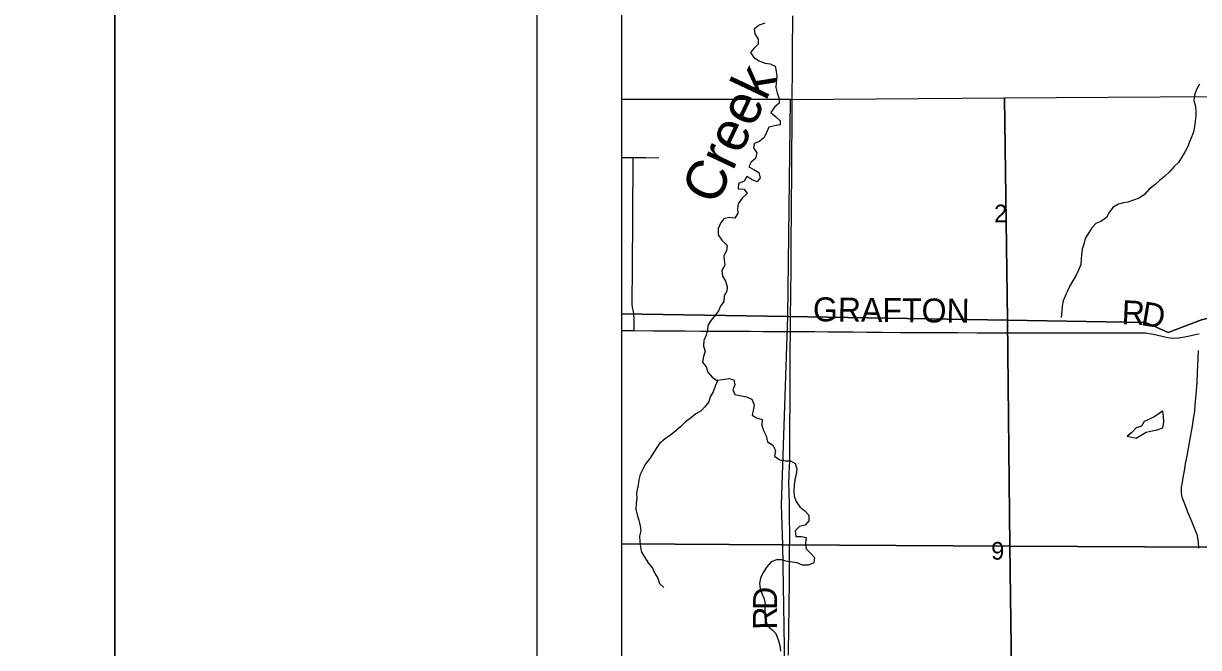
# Model space of a CAD drawing. Extents: x 0 to 34, y 0 to 22.
# Drawn here: x 1.392 to 2.784, y 19.522 to 20.261 of the extents above; entities that cross this region are included whole.
import ezdxf

# ---------------------------------------------------------------- set-up
doc = ezdxf.new("R2010")
doc.units = 0
for name, color, linetype in [('Default', 7, 'Continuous'), ('GM_X_County_Road', 7, 'Continuous'), ('GM_X_County_Road_Text', 7, 'Continuous'), ('GM_X_Minor_Lake', 7, 'Continuous'), ('GM_X_Minor_River', 7, 'Continuous'), ('GM_X_Minor_River_Text', 7, 'Continuous'), ('GM_X_Rail_Line_Text', 7, 'Continuous'), ('GM_X_Section', 7, 'Continuous'), ('GM_X_Section_Text', 7, 'Continuous'), ('GM_X_Township_Road', 7, 'Continuous'), ('SH_Border', 7, 'Continuous'), ('SH_Cut_Line', 7, 'Continuous'), ('SH_Data', 7, 'Continuous')]:
    doc.layers.add(name, color=color, linetype=linetype)

msp = doc.modelspace()

# ---------------------------------------------------------------- linework, layer by layer
at = {"layer": 'Default'}
for points in [[(2.1, 20.1712), (2.1, 19.9174), (2.2971, 19.9141), (2.3001, 20.1712)], [(2.1, 19.9174), (2.1, 19.6448), (2.2913, 19.6437), (2.2898, 19.6911), (2.2971, 19.9141)], [(2.1, 19.6448), (2.1, 19.3789), (2.2957, 19.377), (2.2913, 19.6437)]]:
    msp.add_lwpolyline(points, close=True, dxfattribs=at)
at = {"layer": 'GM_X_County_Road'}
for points in [[(2.298, 19.5128), (2.2981, 19.5252), (2.2982, 19.5351), (2.2984, 19.5502), (2.2987, 19.5642), (2.2988, 19.5786), (2.299, 19.5946), (2.2991, 19.6052), (2.2991, 19.6157), (2.2992, 19.6275), (2.2993, 19.6366), (2.2994, 19.653), (2.2992, 19.679), (2.2992, 19.6895), (2.2987, 19.7071), (2.2985, 19.7168), (2.2987, 19.7257), (2.2993, 19.7382), (2.2994, 19.7405), (2.2995, 19.7524), (2.2997, 19.7647), (2.2997, 19.7814), (2.2999, 19.8154), (2.3, 19.8722), (2.3001, 19.8963), (2.3003, 19.9204), (2.3005, 19.9322), (2.3006, 19.9441), (2.3009, 19.9677), (2.3009, 19.9842), (2.3012, 20.0153), (2.3013, 20.027), (2.3014, 20.039), (2.3016, 20.0578), (2.3017, 20.0721), (2.3018, 20.0918), (2.3019, 20.1113), (2.3021, 20.1363), (2.3024, 20.1609), (2.3024, 20.1749), (2.3026, 20.2063), (2.3027, 20.2284), (2.3028, 20.2424), (2.303, 20.2559), (2.3032, 20.2704)], [(2.1, 19.8976), (2.1042, 19.8976), (2.1151, 19.8974), (2.1373, 19.8973), (2.1562, 19.8972), (2.1755, 19.897), (2.194, 19.8969), (2.2082, 19.8967), (2.2323, 19.8967), (2.253, 19.8966), (2.2675, 19.8965), (2.2839, 19.8964), (2.3001, 19.8963), (2.315, 19.8962), (2.3291, 19.8962), (2.3446, 19.8961), (2.3604, 19.896), (2.3745, 19.8959), (2.3913, 19.8957), (2.4083, 19.8955), (2.4302, 19.8953), (2.4398, 19.8952), (2.4493, 19.8951), (2.4984, 19.895), (2.5215, 19.8949), (2.5406, 19.8949), (2.5555, 19.8948), (2.5721, 19.8947), (2.5896, 19.8946), (2.6903, 19.8947), (2.7038, 19.8948), (2.7149, 19.8949), (2.7186, 19.8948), (2.7211, 19.8946), (2.7253, 19.894), (2.7321, 19.8927), (2.7436, 19.8899), (2.7474, 19.8891), (2.7501, 19.8887), (2.7528, 19.8885), (2.7604, 19.8889), (2.7669, 19.8899), (2.7749, 19.8917), (2.7813, 19.893), (2.7845, 19.8934)]]:
    msp.add_lwpolyline(points, dxfattribs=at)
at = {"layer": 'GM_X_Minor_Lake'}
for points in [[(2.741, 19.8018), (2.7317, 19.7955), (2.7255, 19.7925), (2.7194, 19.7898), (2.7162, 19.7841), (2.7097, 19.7824), (2.7048, 19.7767), (2.6989, 19.7721)], [(2.699, 19.7722), (2.7099, 19.7698), (2.7158, 19.7737), (2.7217, 19.7769), (2.7285, 19.7786), (2.7348, 19.78), (2.7414, 19.7823), (2.7427, 19.7891), (2.7422, 19.7958), (2.7412, 19.8018)], [(2.6991, 19.7722), (2.7099, 19.7698), (2.7158, 19.7737), (2.7217, 19.7769), (2.7285, 19.7786), (2.7348, 19.78), (2.7414, 19.7823), (2.7427, 19.7891), (2.7422, 19.7958), (2.7412, 19.8019)], [(2.7412, 19.8019), (2.7317, 19.7955), (2.7255, 19.7925), (2.7194, 19.7898), (2.7162, 19.7841), (2.7097, 19.7824), (2.7048, 19.7767), (2.6991, 19.7722)]]:
    msp.add_lwpolyline(points, dxfattribs=at)
at = {"layer": 'GM_X_Minor_River'}
for points in [[(2.2697, 20.2616), (2.2633, 20.2593), (2.2574, 20.2547), (2.258, 20.2489), (2.262, 20.2426), (2.262, 20.2367), (2.2568, 20.2318), (2.2529, 20.227), (2.2569, 20.2211), (2.2631, 20.2172), (2.2698, 20.2143), (2.2762, 20.2134), (2.2823, 20.2107), (2.2834, 20.2049), (2.284, 20.1984), (2.2833, 20.1919), (2.2829, 20.1855), (2.2846, 20.1792), (2.2865, 20.1732), (2.2867, 20.1667), (2.2814, 20.1623), (2.2769, 20.1557), (2.283, 20.1507), (2.2879, 20.146), (2.2879, 20.1413), (2.2813, 20.1401), (2.2746, 20.1384), (2.272, 20.1323), (2.2691, 20.1262), (2.2637, 20.1214), (2.2574, 20.1191), (2.2566, 20.1138), (2.2603, 20.1081), (2.2589, 20.1015), (2.2538, 20.0971), (2.2508, 20.0914), (2.2567, 20.0882), (2.2628, 20.0846), (2.2645, 20.0783), (2.2607, 20.0736), (2.255, 20.076), (2.2487, 20.0798), (2.2453, 20.0743), (2.2387, 20.0718), (2.2385, 20.0653), (2.2453, 20.065), (2.2491, 20.0597), (2.2431, 20.0545), (2.2385, 20.0477), (2.2376, 20.0416), (2.2378, 20.0367), (2.2344, 20.0308), (2.2279, 20.0313), (2.2213, 20.0298), (2.2173, 20.0247), (2.2145, 20.0178), (2.2145, 20.011), (2.2191, 20.0045), (2.2253, 19.9983), (2.2246, 19.992), (2.2214, 19.9861), (2.2217, 19.9814), (2.2227, 19.9749), (2.2189, 19.9686), (2.2199, 19.9618), (2.2235, 19.9559), (2.2254, 19.9491), (2.225, 19.9443), (2.2216, 19.9386), (2.2213, 19.9318), (2.2175, 19.9265), (2.2152, 19.9208), (2.2108, 19.9151), (2.2059, 19.9092), (2.2025, 19.9033), (2.2018, 19.8985)], [(2.7846, 20.1894), (2.7814, 20.1829), (2.779, 20.1764), (2.7782, 20.17), (2.7799, 20.1631), (2.7803, 20.1565), (2.7805, 20.1518), (2.7796, 20.1455), (2.7788, 20.1394), (2.7775, 20.1329), (2.7751, 20.1267), (2.7724, 20.1204), (2.7711, 20.1156), (2.7679, 20.1096), (2.7643, 20.1037), (2.7599, 20.0964), (2.7548, 20.0919), (2.7491, 20.0856), (2.7433, 20.0801), (2.7374, 20.0751), (2.7319, 20.0701), (2.7253, 20.0648), (2.7198, 20.0587), (2.7131, 20.0545), (2.7067, 20.0518), (2.6999, 20.0495), (2.6949, 20.0488), (2.6887, 20.0472), (2.6822, 20.0434), (2.6777, 20.0373), (2.6745, 20.0316), (2.668, 20.0265), (2.662, 20.0244), (2.6574, 20.0192), (2.6532, 20.013), (2.6493, 20.0067), (2.6478, 20), (2.6459, 19.9938), (2.6448, 19.9873), (2.6446, 19.9825), (2.6442, 19.9757), (2.6416, 19.9691), (2.6385, 19.963)], [(2.6385, 19.963), (2.6353, 19.9571), (2.6313, 19.9504), (2.6285, 19.9447), (2.6255, 19.9382), (2.6234, 19.9325), (2.6221, 19.9265), (2.6215, 19.9204), (2.6208, 19.9128)], [(2.2018, 19.8985), (2.2004, 19.8921), (2.1978, 19.8856), (2.1974, 19.8791), (2.1991, 19.8732), (2.1973, 19.8668), (2.1959, 19.8599), (2.2005, 19.8543), (2.2024, 19.848), (2.2077, 19.8421), (2.2138, 19.8378), (2.2112, 19.8315), (2.2087, 19.825), (2.2051, 19.8191), (2.2034, 19.8131), (2.1989, 19.8072), (2.1943, 19.8022), (2.1883, 19.799), (2.182, 19.7936), (2.1761, 19.7892), (2.1703, 19.7839), (2.1644, 19.7786), (2.1581, 19.7736), (2.1517, 19.7692), (2.1452, 19.7637), (2.142, 19.759), (2.1337, 19.746), (2.129, 19.7399), (2.1254, 19.7331), (2.1223, 19.7268), (2.1206, 19.7207), (2.1197, 19.7143), (2.1188, 19.7093), (2.118, 19.7046), (2.1182, 19.6987), (2.1175, 19.6922), (2.1169, 19.6858), (2.1188, 19.6793), (2.1207, 19.6727), (2.1221, 19.6662), (2.123, 19.66), (2.1215, 19.6539), (2.1219, 19.6474), (2.1227, 19.641), (2.124, 19.6351), (2.1278, 19.6285), (2.1318, 19.6222), (2.1369, 19.6161), (2.1394, 19.6104), (2.143, 19.6042), (2.1453, 19.5979), (2.1504, 19.593)], [(2.2126, 19.8387), (2.2202, 19.8395), (2.2271, 19.8407), (2.2333, 19.839), (2.2345, 19.8333), (2.2318, 19.8272), (2.2343, 19.8219), (2.248, 19.8189), (2.2544, 19.8162), (2.2571, 19.8096), (2.2562, 19.8029), (2.2548, 19.7971), (2.2602, 19.7942), (2.2668, 19.792), (2.2664, 19.7855), (2.2685, 19.7789), (2.2716, 19.7726), (2.2729, 19.7658), (2.2792, 19.7616), (2.2824, 19.7554), (2.2813, 19.7485), (2.2877, 19.7442), (2.294, 19.743), (2.3003, 19.7432), (2.3059, 19.74), (2.3079, 19.7338), (2.3069, 19.7269), (2.3056, 19.721), (2.3047, 19.7142), (2.3041, 19.7074), (2.3047, 19.7013), (2.3072, 19.6948), (2.3113, 19.6888), (2.3172, 19.6839), (2.322, 19.6787), (2.3222, 19.6721), (2.3178, 19.667), (2.311, 19.6652), (2.3057, 19.6601), (2.3065, 19.6534), (2.3133, 19.6536), (2.3188, 19.6521), (2.318, 19.6457), (2.3188, 19.6389), (2.3241, 19.6337), (2.3289, 19.6286), (2.3281, 19.6222), (2.3213, 19.6197), (2.3147, 19.6195), (2.3082, 19.6221), (2.3018, 19.6232), (2.2949, 19.6244), (2.2902, 19.6257), (2.2837, 19.626), (2.2775, 19.6234), (2.2724, 19.6175), (2.268, 19.6108), (2.2648, 19.6043), (2.2637, 19.5979), (2.2644, 19.592), (2.2663, 19.5859), (2.2692, 19.5798), (2.2702, 19.5734), (2.2698, 19.5667), (2.27, 19.5601), (2.2709, 19.5538), (2.2732, 19.5476), (2.2784, 19.543), (2.283, 19.5384)], [(2.283, 19.5384), (2.2856, 19.5312), (2.2877, 19.5243), (2.2883, 19.5175)]]:
    msp.add_lwpolyline(points, dxfattribs=at)
at = {"layer": 'GM_X_Rail_Line_Text'}
msp.add_lwpolyline([(2.998, 20.3994), (2.6509, 20.3966), (2.5736, 20.3962), (2.2274, 20.395), (2.1893, 20.3948), (2.1, 20.3942), (2.1, 17.7984), (2.1967, 17.7991), (2.2906, 17.7999), (2.7227, 17.8051), (2.7326, 17.8059), (2.7533, 17.8059), (2.7787, 17.8066), (3.0413, 17.8091)], dxfattribs=at)
at = {"layer": 'GM_X_Section'}
for points in [[(2.3001, 20.1712), (2.5539, 20.1731), (2.5574, 19.9097), (2.2971, 19.9141)], [(2.5539, 20.1731), (2.7999, 20.1749), (2.7993, 19.9134), (2.7871, 19.9102), (2.7475, 19.8951), (2.7213, 19.9069), (2.5574, 19.9097)], [(2.2971, 19.9141), (2.5574, 19.9097), (2.56, 19.6422), (2.2913, 19.6437), (2.2898, 19.6911)], [(2.5574, 19.9097), (2.7213, 19.9069), (2.7475, 19.8951), (2.7871, 19.9102), (2.7993, 19.9134), (2.8003, 19.6409), (2.56, 19.6422)], [(2.2913, 19.6437), (2.56, 19.6422), (2.5637, 19.3759), (2.2957, 19.377)], [(2.56, 19.6422), (2.8003, 19.6409), (2.8004, 19.3749), (2.5637, 19.3759)]]:
    msp.add_lwpolyline(points, close=True, dxfattribs=at)
at = {"layer": 'GM_X_Township_Road'}
for points in [[(2.1, 20.1026), (2.1141, 20.1025), (2.129, 20.1024), (2.1443, 20.1023)], [(2.1151, 19.8974), (2.115, 19.9118), (2.1149, 19.9153), (2.1147, 19.9178), (2.1144, 19.9195), (2.114, 19.9216), (2.1133, 19.9246), (2.113, 19.926), (2.1128, 19.928), (2.1128, 19.9302), (2.1129, 19.9451), (2.113, 19.9566), (2.1131, 19.9686), (2.1132, 19.9838), (2.1132, 19.9954), (2.1134, 20.0082), (2.1135, 20.0189), (2.1135, 20.029), (2.1136, 20.0427), (2.1137, 20.057), (2.1138, 20.0773), (2.1139, 20.0895), (2.1141, 20.1025)], [(2.784, 19.6397), (2.7834, 19.6467), (2.7829, 19.6512), (2.7822, 19.6546), (2.7813, 19.6575), (2.7798, 19.6615), (2.7782, 19.6654), (2.7757, 19.6714), (2.771, 19.6822), (2.7668, 19.6929), (2.7653, 19.6969), (2.7644, 19.7002), (2.7638, 19.7026), (2.7635, 19.7049), (2.7634, 19.7073), (2.7635, 19.7103), (2.7636, 19.7122), (2.7641, 19.7154), (2.7657, 19.7254), (2.7668, 19.7311), (2.7683, 19.7396), (2.77, 19.7489), (2.7721, 19.7601), (2.7742, 19.7717), (2.7761, 19.7819), (2.7782, 19.7955), (2.7788, 19.7993), (2.7791, 19.8024), (2.7798, 19.8096), (2.7807, 19.8218), (2.7818, 19.8355), (2.7825, 19.8483), (2.7832, 19.8645), (2.7836, 19.8739)]]:
    msp.add_lwpolyline(points, dxfattribs=at)
at = {"layer": 'SH_Border'}
for points in [[(0.5, 21.5), (1.5, 21.5), (1.5, 0.5), (0.5, 0.5)], [(1.5, 21.5), (33.5, 21.5), (33.5, 0.5), (1.5, 0.5)]]:
    msp.add_lwpolyline(points, close=True, dxfattribs=at)
at = {"layer": 'SH_Cut_Line'}
msp.add_lwpolyline([(2.998, 20.3994), (2.6509, 20.3966), (2.5736, 20.3962), (2.2274, 20.395), (2.1893, 20.3948), (2.1, 20.3942), (2.1, 14.1)], dxfattribs=at)
at = {"layer": 'SH_Data'}
for p, q in [((2, 21), (2, 14)), ((2.1, 20.9), (2.1, 14.1))]:
    msp.add_line(p, q, dxfattribs=at)

# ---------------------------------------------------------------- texts
at = {"layer": 'GM_X_County_Road_Text'}
for s, height, rotation, p in [('GRAFTON', 0.02841, 359.4181, (2.3267, 19.9085)), ('R', 0.0284, 357.4623, (2.6921, 19.9051)), ('D', 0.0284, 350.2784, (2.7145, 19.9042)), ('D', 0.0284, 89.3862, (2.2843, 19.5663)), ('R', 0.0284, 90.6928, (2.2845, 19.5432))]:
    msp.add_text(s, height=height, rotation=rotation, dxfattribs=at).set_placement(p)
at = {"layer": 'GM_X_Minor_River_Text'}
msp.add_text('Creek', height=0.04738, rotation=64.6894, dxfattribs=at).set_placement((2.2123, 20.0443))
at = {"layer": 'GM_X_Section_Text'}
for s, p in [('2', (2.5415, 20.0258)), ('9', (2.538, 19.6261))]:
    msp.add_text(s, height=0.0209, rotation=0, dxfattribs=at).set_placement(p)

doc.saveas('drawing.dxf')
